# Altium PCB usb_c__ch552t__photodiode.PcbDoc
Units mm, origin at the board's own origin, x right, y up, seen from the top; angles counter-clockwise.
Board outline 40 x 21 mm, 2 copper layers (Top, Bottom), stack 0 mm thick; 24 components, 17 nets, 100 pads, 35 vias.
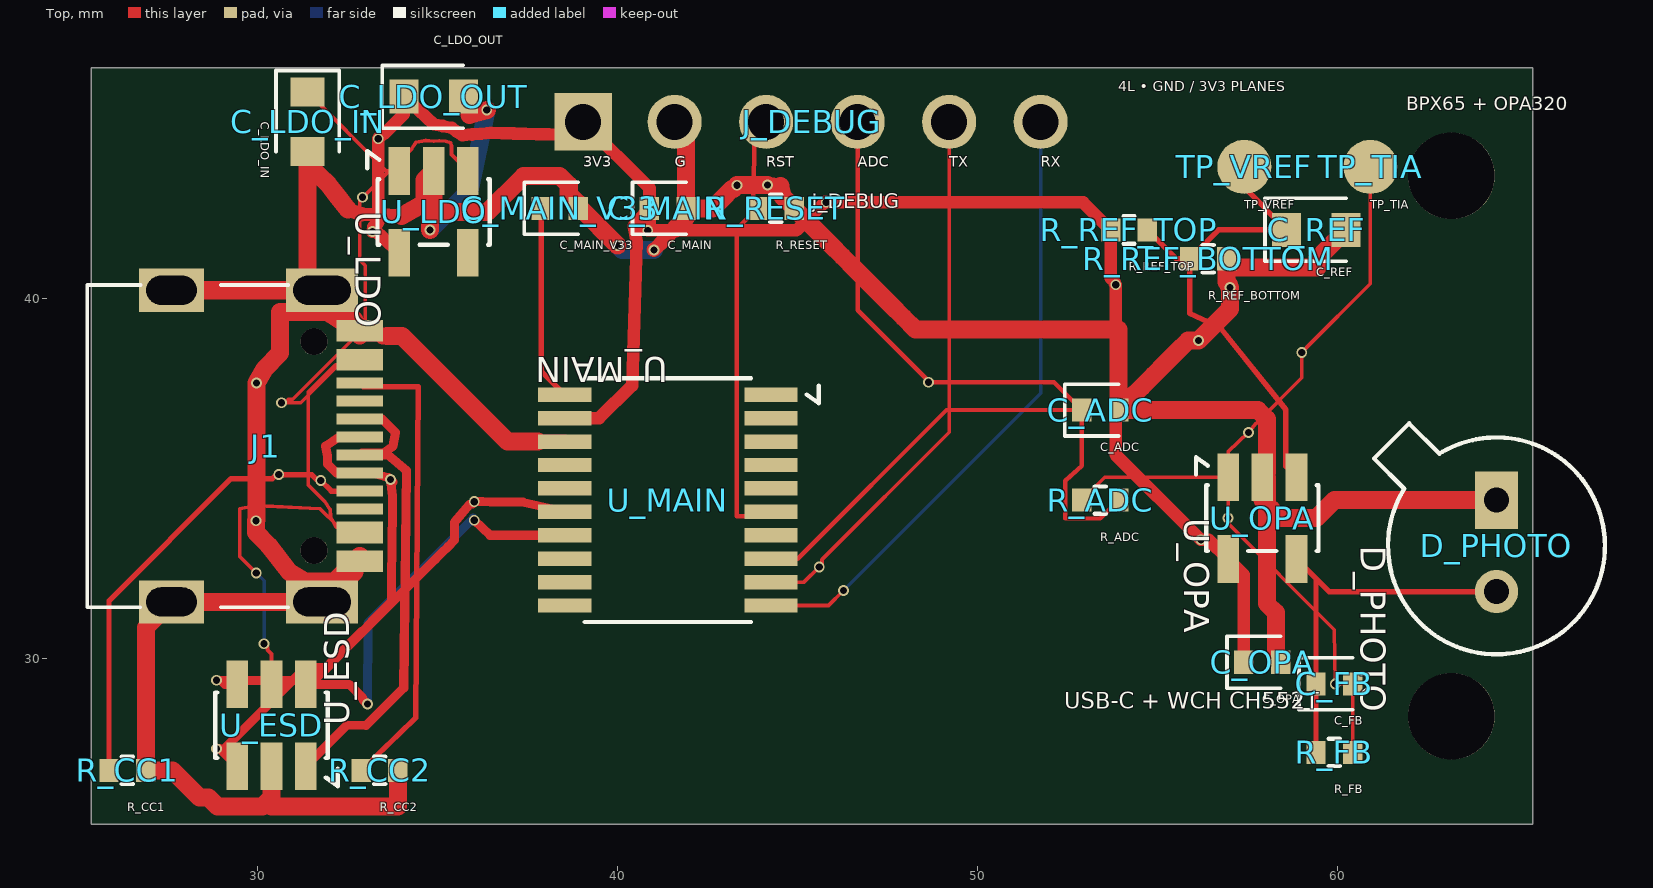
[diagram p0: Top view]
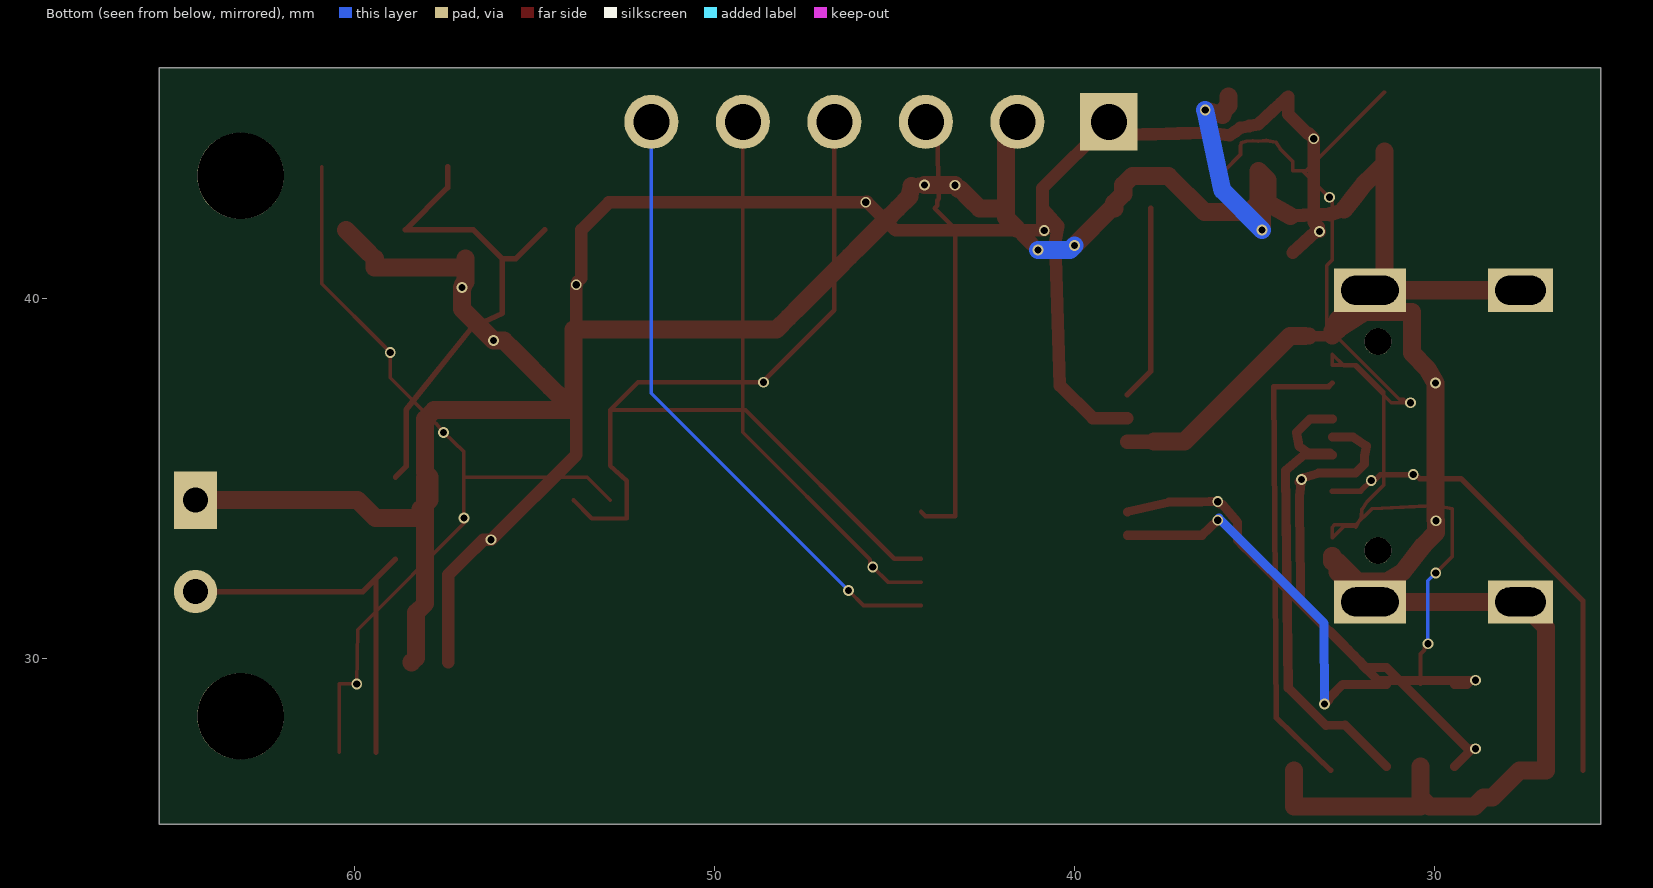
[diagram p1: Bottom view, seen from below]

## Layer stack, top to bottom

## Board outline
25.4,46.4 65.4,46.4 65.4,25.4 25.4,25.4

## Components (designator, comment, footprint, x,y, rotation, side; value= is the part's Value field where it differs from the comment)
C_ADC "" TSCIRCUIT-1.5600x0.6400mm 53.4,36.9 r0 top
C_FB "" TSCIRCUIT-1.5600x0.6400mm 59.9,29.3 r0 top
C_LDO_IN "" TSCIRCUIT-0.9500x2.4500mm 31.4,44.9 r270 top
C_LDO_OUT "" TSCIRCUIT-2.4500x0.9500mm 34.9,45.6 r0 top
C_MAIN "" TSCIRCUIT-1.5600x0.6400mm 41.4,42.5 r0 top
C_MAIN_V33 "" TSCIRCUIT-1.5600x0.6400mm 38.4,42.5 r0 top
C_OPA "" TSCIRCUIT-1.5600x0.6400mm 57.9,29.9 r0 top
C_REF "" TSCIRCUIT-2.4500x0.9500mm 59.4,41.9 r0 top
D_PHOTO "" TSCIRCUIT-1.2000x3.9400mm 64.4,33.23 r270 top
J1 "" TSCIRCUIT-6.7732x9.8502mm 30.113,35.9 r90 top
J_DEBUG "" TSCIRCUIT-14.2000x1.5000mm 45.4,44.9 r0 top
R_ADC "" TSCIRCUIT-1.5600x0.6400mm 53.4,34.4 r0 top
R_CC1 "" TSCIRCUIT-1.5600x0.6400mm 26.4,26.9 r0 top
R_CC2 "" TSCIRCUIT-1.5600x0.6400mm 33.4,26.9 r0 top
R_FB "" TSCIRCUIT-1.5600x0.6400mm 59.9,27.4 r0 top
R_REF_BOTTOM "" TSCIRCUIT-1.5600x0.6400mm 56.4,41.1 r0 top
R_REF_TOP "" TSCIRCUIT-1.5600x0.6400mm 54.2,41.9 r0 top
R_RESET "" TSCIRCUIT-1.5600x0.6400mm 44.4,42.5 r0 top
TP_TIA "" TSCIRCUIT-1.5000x1.5000mm 60.9,43.65 r0 top
TP_VREF "" TSCIRCUIT-1.5000x1.5000mm 57.4,43.65 r0 top
U_ESD "" TSCIRCUIT-2.5000x3.6000mm#1 30.4,28.15 r90 top
U_LDO "" TSCIRCUIT-2.5000x3.6000mm#2 34.9,42.4 r270 top
U_MAIN "" TSCIRCUIT-7.2000x6.2500mm 41.4,34.4 r180 top
U_OPA "" TSCIRCUIT-2.5000x3.6000mm#2 57.9,33.9 r270 top

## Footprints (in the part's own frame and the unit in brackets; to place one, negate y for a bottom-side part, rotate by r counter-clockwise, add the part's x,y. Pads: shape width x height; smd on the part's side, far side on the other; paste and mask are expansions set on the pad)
TSCIRCUIT-0.9500x2.4500mm [mm]
  rect 0.8x0.95 smd: 1(-0.825,0) 2(0.825,0)
  silkscreen extent -1.43,-0.87 0.82,0.87
TSCIRCUIT-1.2000x3.9400mm [mm]
  rect 1.6x1.2 hole 0.7: 1(-1.17,0)
  round 1.2 hole 0.7: 2(1.37,0)
  silkscreen extent -3.3,-3.4 3.11,3.01
TSCIRCUIT-1.5000x1.5000mm [mm]
  round 1.5 smd: 1(0,0)
TSCIRCUIT-1.5600x0.6400mm [mm]
  rect 0.54x0.64 smd: 1(-0.51,0) 2(0.51,0)
  silkscreen extent -0.98,-0.72 0.51,0.72
TSCIRCUIT-2.4500x0.9500mm [mm]
  rect 0.8x0.95 smd: 1(-0.825,0) 2(0.825,0)
  silkscreen extent -1.42,-0.87 0.83,0.87
TSCIRCUIT-2.5000x3.6000mm#1 [mm]
  rect 1.325x0.6 smd: 1(-1.137,-0.95) 2(-1.137,0) 3(-1.137,0.95) 4(1.138,0.95) 5(1.138,0) 6(1.138,-0.95)
  silkscreen extent -1.69,-1.84 0.91,1.56
TSCIRCUIT-2.5000x3.6000mm#2 [mm]
  rect 1.325x0.6 smd: 1(-1.138,-0.95) 2(-1.138,0) 3(-1.138,0.95) 4(1.137,0.95) 5(1.137,-0.95)
  silkscreen extent -1.69,-1.84 0.91,1.56
TSCIRCUIT-6.7732x9.8502mm [mm]
  rect 0.3x1.3 smd: 1(-3.35,-2.737) 2(-3.05,-2.737) 3(-2.55,-2.737) 4(-2.25,-2.737) 5(-1.75,-2.737) 6(-1.25,-2.737) 7(-0.75,-2.737) 8(-0.25,-2.737) 9(0.25,-2.737) 10(0.75,-2.737) 11(1.25,-2.737) 12(1.75,-2.737) 13(2.55,-2.737) 14(2.25,-2.737) 15(3.35,-2.737) 16(3.05,-2.737)
  rect 1.2x2 hole 0.8 slot 1.6 at 90 deg: 17(-4.325,-1.693) 18(4.325,-1.693)
  rect 1.2x1.8 hole 0.8 slot 1.4 at 90 deg: 19(4.325,2.487) 20(-4.325,2.487)
  round 0.75 hole 0.75 unplated: NPTH-1(-2.9,-1.468) NPTH-2(2.9,-1.468)
  silkscreen extent -4.47,-0.75 4.47,4.83
TSCIRCUIT-7.2000x6.2500mm [mm]
  rect 1.475x0.4 smd: 1(-2.862,-2.925) 2(-2.862,-2.275) 3(-2.862,-1.625) 4(-2.862,-0.975) 5(-2.862,-0.325) 6(-2.862,0.325) 7(-2.862,0.975) 8(-2.862,1.625) 9(-2.862,2.275) 10(-2.862,2.925) 11(2.863,2.925) 12(2.863,2.275) 13(2.863,1.625) 14(2.863,0.975) 15(2.863,0.325) 16(2.863,-0.325) 17(2.863,-0.975) 18(2.863,-1.625) 19(2.863,-2.275) 20(2.863,-2.925)
  silkscreen extent -4.19,-3.38 2.31,3.38
TSCIRCUIT-14.2000x1.5000mm [mm]
  rect 1.6x1.6 hole 1: 1(-6.35,0)
  round 1.5 hole 1: 2(-3.81,0) 3(-1.27,0) 4(1.27,0) 5(3.81,0) 6(6.35,0)

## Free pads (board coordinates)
  round 2.4 hole 2.4 unplated: NPTH-3(63.15,43.4) NPTH-4(63.15,28.4)

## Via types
v1: diameter 0.3, hole 0.2, Top to Bottom, 35 vias

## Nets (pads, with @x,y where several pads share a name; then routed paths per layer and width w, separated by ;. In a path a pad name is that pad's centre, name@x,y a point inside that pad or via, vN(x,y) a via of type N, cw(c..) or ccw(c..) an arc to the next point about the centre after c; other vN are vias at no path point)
ADC_IN: C_ADC.1 J_DEBUG.4 R_ADC.2 U_MAIN.8 | length 27.9
  Top w0.12: U_MAIN.8 44.265,32.772 45.006,32.772 49.134,36.9 C_ADC.1 ; J_DEBUG.4 46.67,39.667 48.627,37.711 48.627,37.682 v1(48.637,37.672) 52.118,37.672 C_ADC.1 ; R_ADC.2 53.4,33.89 52.674,33.89 52.43,33.89 52.43,34.936 52.89,35.356 C_ADC.1
GND: C_ADC.2 C_LDO_IN.2 C_LDO_OUT.2 C_MAIN.2 C_MAIN_V33.2 C_OPA.2 C_REF.2 D_PHOTO.1 J1.1 J1.2 J1.15 J1.16 J1.17 J1.18 J1.19 J1.20 J_DEBUG.2 R_CC1.2 R_CC2.2 R_REF_BOTTOM.2 R_RESET.2 U_ESD.2 U_LDO.2 U_MAIN.18 U_OPA.2 | length 120.4
  Top w0.3: J1.1@32.699,32.4 J1.1 J1.2@32.849,32.7 ; J1.1@32.699,32.7 J1.2 ; J1.15@32.699,39.1 J1.16 32.943,38.95 33.037,38.95 33.13,38.95 33.224,38.95 33.318,38.95 33.412,38.95 33.499,38.95 ; 32.699,39.4 J1.15 J1.16@32.849,39.1
  Top w0.375: 32.9,42.337 33.268,42.321 33.637,42.304 34.005,42.288
  Top w0.4: 32.525,42.463 32.9,42.337 ; U_MAIN.18@37.8,36.025 U_MAIN.18 ; v1(41.015,41.344) 41.313,41.642 41.612,41.941
  Top w0.45: v1(44.17,43.149) 44.525,43.119
  Top w0.475: J1.15@32.285,39.397 32.624,39.175 J1.16@32.699,39.1 ; J1.16 J1.15@32.849,39.1 ; 33.499,38.95 33.505,38.95 33.599,38.95
  Top w0.5: J1.19 J1.18 ; J1.15@32.285,39.397 31.947,39.619 30.637,39.619 30.637,38.832 30.637,38.479 30.202,38.045 v1(29.985,37.651) 29.985,33.848 v1(29.967,33.83) 29.967,33.499 30.306,33.16 30.9,32.4 31.322,32.144 32.143,32.144 32.174,32.175 J1.1@32.699,32.7 ; 32.525,42.463 32.252,42.809 31.979,43.155 31.687,43.441 31.396,43.728 C_LDO_IN.2 31.4,40.631 J1.18 ; J1.1@32.699,32.4 32.474,32.175 31.874,31.575 J1.17 J1.20 26.91,30.859 R_CC1.2 27.65,26.9 28.4,26.15 28.65,26.15 28.9,25.9 30.15,25.9 30.4,26.15 U_ESD.2 30.4,25.9 33.91,25.9 R_CC2.2 ; 32.699,39.4 32.474,39.625 31.874,40.225 J1.18 ; J1.1@32.849,32.7 J1.2 ; 33.599,38.95 34.024,38.95 36.949,36.025 37.8,36.025 ; 34.005,42.288 34.65,42.65 34.65,43.288 U_LDO.2 ; v1(34.8,41.9) 34.8,43.437 U_LDO.2 ; C_LDO_OUT.2 35.725,45.348 35.901,45.173 35.902,45.09 v1(36.375,45.225) ; v1(40.004,41.468) 38.972,42.5 C_MAIN_V33.2 38.9,42.49 38.9,42.65 38.65,42.9 38.65,43.15 38.4,43.4 37.4,43.4 36.4,42.4 35.15,42.4 34.9,42.65 U_LDO.2 ; J_DEBUG.2 41.91,44.58 C_MAIN.2 ; 41.612,41.941 41.91,42.239 C_MAIN.2 ; v1(44.17,43.149) 44.161,43.14 v1(43.323,43.14) 43.225,43.042 43.185,43.042 42.915,42.771 42.644,42.5 42.277,42.5 C_MAIN.2 ; 44.525,43.119 44.585,42.824 R_RESET.2 45.246,42.164 45.582,41.828 45.918,41.492 46.254,41.156 46.59,40.82 46.926,40.484 47.263,40.147 47.599,39.811 47.935,39.475 48.271,39.139 53.91,39.139 C_ADC.2 ; C_OPA.2 58.4,29.9 58.275,30.025 58.275,31.275 58.025,31.525 58.025,35.025 57.913,35.025 U_OPA.2 ; C_REF.2 59.958,41.633 59.692,41.367 59.425,41.1 59.425,40.85 56.91,40.85 R_REF_BOTTOM.2 56.91,40.775 56.91,40.45 56.981,40.379 56.981,40.319 v1(57,40.3) 57,40.001 57,39.703 56.729,39.432 56.458,39.161 56.186,38.889 v1(56.131,38.834) 55.844,38.834 55.522,38.512 55.199,38.189 54.877,37.867 54.555,37.545 54.232,37.222 C_ADC.2 ; D_PHOTO.1 59.9,34.4 59.4,33.9 58.15,33.9 58.15,34.15 57.9,34.4 U_OPA.2 ; C_ADC.2 54.406,36.9 54.902,36.9 55.398,36.9 55.893,36.9 56.389,36.9 56.885,36.9 57.775,36.9 58.025,36.65 58.025,35.4 58.025,35.163 U_OPA.2
  Bottom w0.5: v1(34.8,41.9) 34.822,41.922 35.899,42.999 v1(36.375,45.225) ; v1(40.004,41.468) 40.128,41.344 v1(41.015,41.344)
MAIN_RESET: J_DEBUG.3 R_RESET.1 U_MAIN.6 | length 12.4
  Top w0.12: J_DEBUG.3 43.816,44.586 43.767,42.771 43.78,42.74 43.816,42.719 43.816,42.574 R_RESET.1 43.313,41.923 43.313,33.953 44.14,33.953 U_MAIN.6
MAIN_V33: C_MAIN_V33.1 U_MAIN.20 | length 5.4
  Top w0.15: C_MAIN_V33.1 37.89,37.972 U_MAIN.20
PD_SUM: C_FB.1 D_PHOTO.2 R_FB.1 U_OPA.4 | length 11.5
  Top w0.15: R_FB.1 C_FB.1 59.39,32.222 U_OPA.4 59.752,31.86 D_PHOTO.2
TIA_OUT: C_FB.2 R_ADC.1 R_FB.2 TP_TIA.1 U_OPA.1 | length 24
  Top w0.1: R_ADC.1 53.528,35.037 U_OPA.1 56.95,35.749 v1(57.513,36.274) 57.729,36.528 58.997,37.796 v1(58.997,38.499) 59.129,38.631 59.129,38.634 60.9,40.405 TP_TIA.1 ; U_OPA.1 v1(56.95,33.9) 56.887,33.837 56.867,33.837 59.9,30.804 v1(59.925,29.3) 59.93,29.33 59.96,29.3 C_FB.2 R_FB.2
UART_MAIN_RX: J_DEBUG.6 U_MAIN.10 | length 17.5
  Top w0.1: U_MAIN.10 45.859,31.475 v1(46.272,31.888)
  Bottom w0.1: v1(46.272,31.888) 46.294,31.91 51.75,37.366 J_DEBUG.6
UART_MAIN_TX: J_DEBUG.5 U_MAIN.9 | length 15.4
  Top w0.1: U_MAIN.9 45.18,32.125 v1(45.601,32.546) 45.678,32.623 45.678,32.75 49.21,36.281 J_DEBUG.5
USB_CC1: J1.6 R_CC1.1 | length 13.3
  Top w0.15: R_CC1.1 25.89,31.605 29.28,34.995 30.426,34.995 30.5,35.069 30.564,35.069 v1(30.602,35.107) 31.513,35.107 31.721,34.9 v1(31.767,34.946) 32.063,34.65 J1.6
USB_CC2: J1.12 R_CC2.1 | length 13
  Top w0.15: J1.12 32.951,37.548 34.475,37.547 34.401,28.353 R_CC2.1
USB_DM_MCU: U_ESD.4 U_MAIN.15 | length 12.7
  Top w0.25: U_ESD.4 29.28,29.288 29.109,29.288 28.997,29.4 v1(28.874,29.4) 29.121,29.4 29.367,29.4 29.614,29.4 29.861,29.4 30.107,29.4 30.354,29.4 30.6,29.4 30.847,29.4 31.094,29.4 31.34,29.4 31.587,29.4 31.764,29.577 31.941,29.754 32.117,29.93 32.294,30.107 32.471,30.284 32.648,30.461 32.824,30.637 33.001,30.814 33.178,30.991 33.355,31.168 33.531,31.345 33.708,31.521 33.885,31.698 34.062,31.875 34.239,32.052 34.415,32.228 34.592,32.405 34.769,32.582 34.946,32.759 35.122,32.935 35.299,33.112 35.476,33.289 35.475,33.537 35.475,33.785 35.9,34.275 35.981,34.292 v1(36.025,34.358) 36.25,34.355 36.476,34.353 36.701,34.35 36.927,34.348 37.153,34.345 37.378,34.343 U_MAIN.15
USB_DM_PORT: J1.7 J1.9 U_ESD.3 | length 14.5
  Top w0.25: U_ESD.3 29.287,27.175 29.125,27.337 28.962,27.5 v1(28.874,27.5) 28.876,27.498 29.087,27.498 29.26,27.672 29.434,27.845 29.607,28.019 29.78,28.192 29.954,28.366 30.127,28.539 30.301,28.712 30.474,28.886 30.647,29.059 30.821,29.233 30.994,29.406 31.168,29.579 31.341,29.753 31.528,29.753 31.715,29.753 31.901,29.753 32.067,29.919 32.233,30.084 32.399,30.25 32.564,30.416 32.73,30.582 32.896,30.748 32.9,30.712 33.228,31.079 33.393,31.245 33.559,31.411 33.725,31.576 33.728,31.82 33.731,32.064 33.734,32.308 33.737,32.552 33.74,32.796 33.743,33.04 33.746,33.284 33.749,33.528 33.752,33.772 33.755,34.016 33.758,34.26 33.761,34.504 v1(33.7,34.975) 33.725,34.838 33.775,34.9 33.65,35.025 33.225,35.15 33.037,35.15 J1.7 32.635,35.15 32.422,35.15 32.208,35.15 32.082,35.276 31.956,35.402 31.956,35.62 31.9,35.9 32.267,36.15 32.461,36.15 32.655,36.15 J1.9
USB_DP_MCU: U_ESD.6 U_MAIN.14 | length 11.1
  Top w0.25: U_ESD.6 32.552,29.288 32.94,28.9 32.94,28.862 v1(33.064,28.738) ; v1(36.028,33.84) 36.467,33.425 U_MAIN.14
  Bottom w0.25: v1(33.064,28.738) 33.078,30.982 35.994,33.898 v1(36.028,33.84)
USB_DP_PORT: J1.8 J1.10 U_ESD.1 | length 13.7
  Top w0.25: U_ESD.1 32.493,28.155 33.028,28.145 34.071,29.191 34.141,35.221 33.631,35.65 J1.8 32.907,35.708 33.106,35.708 33.305,35.708 33.505,35.708 33.775,35.9 33.846,36.275 33.721,36.4 33.596,36.525 33.471,36.65 33.264,36.65 33.057,36.65 J1.10
VBUS5: C_LDO_IN.1 J1.3 J1.4 J1.13 J1.14 U_ESD.5 U_LDO.1 U_LDO.3 | length 33.3
  Top w0.1: v1(29.979,32.376) 29.519,32.836 29.519,34.156 29.95,34.25 31.756,34.156 32.237,33.675 32.525,33.675 J1.3 J1.4 32.786,33.713 32.176,33.713 32.199,33.65 32.037,33.936 32.028,34.142 31.868,34.374 31.415,34.827 31.415,37.387 32.178,38.15 J1.14 J1.13 32.524,38.126 32.237,38.126 31.212,37.1 v1(30.679,37.1) 30.695,37.116 30.776,37.116 30.864,37.203 30.989,37.203 33.001,39.215 33.001,39.368 33.001,40.909 32.855,41.056 32.855,42.721 v1(32.926,42.805) 32.989,42.855 33.671,43.537 U_LDO.1 ; v1(30.195,30.414) 30.289,30.32 30.289,30.242 30.4,30.131 U_ESD.5 ; C_LDO_IN.1 33.588,43.537 U_LDO.1 ; U_LDO.3 35.395,43.992 35.395,44.232 35.37,44.317 35.232,44.359 35.06,44.372 34.899,44.365 34.683,44.382 34.411,44.334 34.29,44.147 33.95,43.806 U_LDO.1
  Bottom w0.1: v1(29.979,32.376) 30.017,32.338 30.195,32.16 v1(30.195,30.414)
VCC_3V3: C_LDO_OUT.1 C_MAIN.1 C_OPA.1 J_DEBUG.1 R_REF_TOP.1 U_LDO.5 U_MAIN.19 U_OPA.5 | length 48.9
  Top w0.35: U_LDO.5 33.312,41.851 v1(33.2,41.852) 33.229,41.929 33.229,41.987 33.368,42.117 v1(33.363,44.432) 33.502,44.575 33.533,44.575 34.075,45.117 C_LDO_OUT.1 34.282,45.409 34.488,45.218 34.695,45.027 34.902,44.836 35.149,44.783 35.396,44.73 35.549,44.628 35.702,44.526 35.964,44.549 36.226,44.572 36.488,44.595 36.808,44.586 37.128,44.577 37.448,44.568 37.768,44.559 38.088,44.55 38.408,44.541 38.727,44.532 38.889,44.716 J_DEBUG.1 40.89,43.06 C_MAIN.1 ; U_MAIN.19 39.494,36.675 40.407,37.581 40.541,41.57 40.456,42.01 C_MAIN.1 ; C_OPA.1 57.39,32.322 U_OPA.5 56.414,33.298 v1(56.197,33.298) 56.186,33.309 56.18,33.309 53.83,35.66 v1(53.83,40.378) 53.808,40.4 53.808,40.449 53.69,40.566 R_REF_TOP.1 52.924,42.666 v1(45.795,42.666) 45.78,42.681 45.762,42.681 44.968,41.886 v1(40.843,41.886) 40.812,41.917 40.812,42.033 40.89,42.111 C_MAIN.1
VREF_0V5: C_REF.1 R_REF_BOTTOM.1 R_REF_TOP.2 TP_VREF.1 U_OPA.3 | length 14.1
  Top w0.15: R_REF_TOP.2 55.51,41.1 R_REF_BOTTOM.1 ; TP_VREF.1 57.4,43.075 C_REF.1 56.69,41.9 R_REF_BOTTOM.1 ; U_OPA.3 58.555,35.332 58.555,36.914 56.71,39.21 55.89,39.579 R_REF_BOTTOM.1
pads on no net: J1.5 J1.11 J1.NPTH-1 J1.NPTH-2 U_LDO.4 U_MAIN.1 U_MAIN.2 U_MAIN.3 U_MAIN.4 U_MAIN.5 U_MAIN.7 U_MAIN.11 U_MAIN.12 U_MAIN.13 U_MAIN.16 U_MAIN.17

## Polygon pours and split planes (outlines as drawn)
GND on Mid1 (solid): 65.1,46.1 25.7,46.1 25.7,25.7 65.1,25.7 65.1,31.38 65.001,31.259 64.872,31.153 64.725,31.075 64.566,31.026 64.4,31.01 64.234,31.026 64.075,31.075 63.928,31.153 63.799,31.259 63.693,31.388 63.615,31.535 63.566,31.694 63.55,31.86 63.566,32.026 63.615,32.185 63.693,32.332 63.799,32.461 63.928,32.567 64.075,32.645 64.234,32.694 64.4,32.71 64.566,32.694 64.725,32.645 64.872,32.567 65.001,32.461 65.1,32.34 65.1,33.72 65.001,33.599 64.872,33.493 64.725,33.415 64.566,33.366 64.55,33.365 64.55,33.622 64.63,33.646 64.733,33.701 64.824,33.776 64.899,33.867 64.954,33.97 64.988,34.083 65,34.2 65,34.25 65.1,34.25 65.1,34.55 65,34.55 65,34.6 64.988,34.717 64.954,34.83 64.899,34.933 64.824,35.024 64.733,35.099 64.63,35.154 64.55,35.178 64.55,35.435 64.566,35.434 64.725,35.385 64.872,35.307 65.001,35.201 65.1,35.08
VCC_3V3 on Mid2 (solid): 65.1,46.1 25.7,46.1 25.7,25.7 65.1,25.7 65.1,31.38 65.001,31.259 64.872,31.153 64.725,31.075 64.566,31.026 64.4,31.01 64.234,31.026 64.075,31.075 63.928,31.153 63.799,31.259 63.693,31.388 63.615,31.535 63.566,31.694 63.55,31.86 63.566,32.026 63.615,32.185 63.693,32.332 63.799,32.461 63.928,32.567 64.075,32.645 64.234,32.694 64.4,32.71 64.566,32.694 64.725,32.645 64.872,32.567 65.001,32.461 65.1,32.34 65.1,33.72 65.001,33.599 64.872,33.493 64.725,33.415 64.566,33.366 64.4,33.35 64.234,33.366 64.075,33.415 63.928,33.493 63.799,33.599 63.693,33.728 63.615,33.875 63.566,34.034 63.55,34.2 63.55,34.6 63.566,34.766 63.615,34.925 63.693,35.072 63.799,35.201 63.928,35.307 64.075,35.385 64.234,35.434 64.4,35.45 64.566,35.434 64.725,35.385 64.872,35.307 65.001,35.201 65.1,35.08

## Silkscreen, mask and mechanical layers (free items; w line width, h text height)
Top Overlay:
  text "4L • GND / 3V3 PLANES" at 53.9,45.65 h0.48
  text "BPX65 + OPA320" at 61.9,45.1 h0.65
  text "USB-C + WCH CH552T" at 52.4,28.45 h0.78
